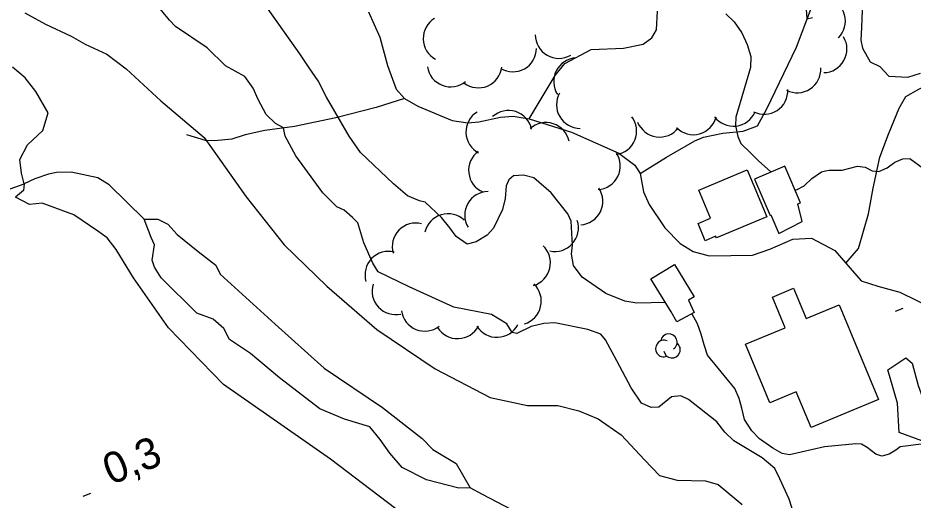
# Model space of a CAD drawing. Extents: x 362852 to 366875, y 5563573 to 5566479.
# Drawn here: x 363430.9 to 363544.5, y 5564422.3 to 5564483.5 of the extents above; entities that cross this region are included whole.
import ezdxf

# ---------------------------------------------------------------- set-up
doc = ezdxf.new("R2010")
doc.units = 0
for name, color, linetype in [('Niveau 19', 7, 'Continuous'), ('Niveau 2', 7, 'Continuous'), ('Niveau 22', 7, 'Continuous'), ('Niveau 3', 7, 'Continuous'), ('Niveau 31', 7, 'Continuous'), ('Niveau 4', 7, 'Continuous'), ('Niveau 44', 7, 'Continuous'), ('Niveau 7', 7, 'Continuous')]:
    doc.layers.add(name, color=color, linetype=linetype)

msp = doc.modelspace()

# ---------------------------------------------------------------- linework, layer by layer
at = {"layer": 'Niveau 19'}
msp.add_lwpolyline([(363555.06, 5564410.53), (363554.35, 5564413.76), (363552.74, 5564417.08), (363550.97, 5564420.84), (363547.82, 5564426.2), (363545.6, 5564429.8), (363542.71, 5564430.86), (363542.49, 5564434.61), (363541.27, 5564438.82), (363543.56, 5564440.35), (363544.37, 5564439.68), (363545.12, 5564436.85), (363545.65, 5564435.43), (363546.72, 5564433.62), (363550.3, 5564428.94), (363553.77, 5564422.9), (363555.22, 5564419.83), (363557.05, 5564416.78)], dxfattribs=at)
at = {"layer": 'Niveau 2'}
for points in [[(363469.58, 5564461.32), (363466.16, 5564466.03), (363464.8, 5564468.53), (363464.56, 5564469.55), (363463.56, 5564470.14), (363462.39, 5564471.28), (363461.35, 5564473.16), (363460.74, 5564474.6), (363459.68, 5564476.09), (363457.23, 5564477.45), (363454.89, 5564479.73), (363450.87, 5564482.43), (363450.1, 5564483.23), (363448.52, 5564485.2)], [(363530.86, 5564485.24), (363531, 5564483.42), (363531.74, 5564483.6)], [(363538.06, 5564485.57), (363537.92, 5564482.31), (363537.84, 5564480.71), (363538.08, 5564479.69), (363539.06, 5564477.96), (363540.26, 5564477.34), (363541.4, 5564476.13), (363543.82, 5564476.02), (363545.43, 5564476.51)], [(363482.58, 5564460.13), (363481.82, 5564460.31), (363480.31, 5564460.93), (363478.55, 5564462.44), (363474.36, 5564466.45), (363472.92, 5564468.53), (363470.04, 5564473.46), (363468.99, 5564475.52), (363467.85, 5564477.17), (363466.65, 5564478.98), (363462.54, 5564484.77)], [(363520.72, 5564484.04), (363521.77, 5564483.04), (363522.74, 5564481.64), (363523.42, 5564480.17), (363523.88, 5564478.61), (363523.84, 5564477.22), (363521.98, 5564470.93)], [(363521.98, 5564470.93), (363521.93, 5564469.84), (363522.26, 5564468.48), (363522.64, 5564467.57), (363523.9, 5564466.35), (363524.87, 5564465.38), (363526.44, 5564463.96)], [(363529.47, 5564461.74), (363529.67, 5564461.7), (363530.66, 5564462.18), (363531.63, 5564463.15), (363532.85, 5564463.97), (363533.35, 5564464.12), (363533.82, 5564464.19), (363535.5, 5564464.21), (363537.42, 5564464.71), (363538.42, 5564464.56), (363539.3, 5564464.12), (363540.14, 5564464.03), (363541.21, 5564464.48), (363542.16, 5564465.19), (363543.17, 5564465.62), (363544.08, 5564465.69), (363545.8, 5564464.41), (363547.73, 5564462.53)], [(363501.07, 5564457.7), (363500.66, 5564458.65), (363498.54, 5564461.33), (363496.36, 5564463.23), (363495.04, 5564463.55), (363493.77, 5564463.46), (363493.16, 5564462.95), (363492.86, 5564462.2), (363492.72, 5564460.58), (363492.37, 5564459.18), (363491.23, 5564456.82), (363490.42, 5564455.92), (363489.02, 5564455.08), (363487.89, 5564454.79), (363486.48, 5564455.76), (363485.7, 5564456.88), (363484.65, 5564458.19), (363482.58, 5564460.13)], [(363529.38, 5564420.42), (363528.74, 5564422.41), (363527.59, 5564424.99), (363526.92, 5564426.28), (363525.35, 5564427.63), (363521.74, 5564429.81), (363520.59, 5564430.9), (363519.59, 5564432.23), (363515.97, 5564435.04), (363515.02, 5564435.51), (363513.82, 5564435.39), (363512.23, 5564434.09), (363511.24, 5564434.05), (363510.01, 5564434.6), (363508.69, 5564436.56), (363506.87, 5564439.99), (363505.44, 5564442.65), (363504.84, 5564443.34), (363503.2, 5564443.97), (363499.03, 5564444.78), (363497.62, 5564444.7), (363496.02, 5564444.34), (363494.2, 5564443.45), (363493.59, 5564443.56), (363492.93, 5564444.67), (363490.99, 5564445.86), (363486.21, 5564446.8), (363480.55, 5564449.38), (363476.61, 5564451.29), (363475.91, 5564452.38), (363474.76, 5564454.97), (363474.02, 5564457.48), (363473.34, 5564458.19), (363472.26, 5564459.12), (363471.33, 5564459.54), (363469.58, 5564461.32)], [(363513.06, 5564447.36), (363509.43, 5564447.31), (363507.9, 5564447.54), (363505.48, 5564448.53), (363502.49, 5564450.59), (363501.37, 5564452.06), (363501.13, 5564453.53), (363501.28, 5564454.66), (363501.07, 5564457.7)], [(363545.83, 5564429.42), (363542.83, 5564429.04), (363542.31, 5564428.64), (363541.47, 5564428.1), (363540.5, 5564427.88), (363539.77, 5564428.13), (363538.66, 5564428.98), (363537.93, 5564429.37), (363537.21, 5564429.44), (363533.26, 5564429.03), (363528.8, 5564428.03), (363527.85, 5564428.2), (363526.68, 5564428.89), (363525, 5564430.07), (363524.01, 5564431.09), (363523.09, 5564432.52), (363522.75, 5564433.94), (363522.41, 5564435.18), (363521.88, 5564436.45), (363518.41, 5564440.69), (363517.98, 5564442.01), (363517.6, 5564443.36), (363517.12, 5564444.66), (363516.4, 5564445.97)]]:
    msp.add_lwpolyline(points, dxfattribs=at)
at = {"layer": 'Niveau 22'}
for points in [[(363509.85, 5564463.76), (363513.2, 5564465.86), (363516.77, 5564467.92), (363517.89, 5564468.39), (363520.35, 5564468.9), (363522.9, 5564469.13), (363524.72, 5564469.81), (363525.93, 5564472), (363529.68, 5564479.82), (363531.84, 5564485.53), (363533.38, 5564487.61), (363535.37, 5564491.01), (363537.09, 5564495.12), (363538.96, 5564504.55), (363539.15, 5564510.65), (363540.17, 5564515.15), (363540.56, 5564522.28), (363540.7, 5564529.49), (363541.26, 5564531.67), (363543.86, 5564536.02)], [(363475.38, 5564484.29), (363476.81, 5564481.07), (363477.79, 5564477.48), (363478.9, 5564474.5), (363479.95, 5564473.31), (363481.64, 5564472.33), (363485.97, 5564470.49), (363487.98, 5564470.19), (363489.36, 5564470.33), (363492.11, 5564470.93), (363493.75, 5564471.05), (363495.75, 5564470.71), (363501.12, 5564469.03), (363507.13, 5564466.37), (363509.15, 5564464.84), (363509.85, 5564463.76), (363510.29, 5564461.44), (363510.99, 5564459.85), (363512.99, 5564456.87), (363514.93, 5564454.87), (363516.59, 5564453.88), (363518.6, 5564453.29), (363524.11, 5564453.41), (363526.3, 5564454.15), (363529.23, 5564455.43), (363531.59, 5564455.54), (363534.54, 5564453.97), (363535.96, 5564452.36), (363537.9, 5564450.15), (363540.02, 5564449.44), (363542.79, 5564448.68), (363547.12, 5564446.56)], [(363495.75, 5564470.71), (363497.55, 5564473.66), (363499.08, 5564476.23), (363500.3, 5564477.75), (363503.64, 5564479.53), (363507.72, 5564479.69), (363510.24, 5564480.19), (363511.33, 5564481.02), (363511.91, 5564482.02), (363512.04, 5564484.39)], [(363535.96, 5564452.36), (363537.56, 5564454.25), (363538.81, 5564458.65), (363539.41, 5564461.9), (363540.28, 5564465.84), (363541.38, 5564468.78), (363542.74, 5564472.08), (363543.57, 5564473.54), (363545.21, 5564474.48), (363548.01, 5564475.79), (363551.55, 5564477.49)], [(363479.95, 5564473.31), (363476.34, 5564472.15), (363471.21, 5564470.84), (363465.96, 5564469.72), (363462.21, 5564469.24), (363459.72, 5564468.67), (363458.04, 5564468.14), (363455.83, 5564467.9), (363454.69, 5564467.98), (363452.3, 5564468.68)]]:
    msp.add_lwpolyline(points, dxfattribs=at)
at = {"layer": 'Niveau 3'}
for p, q in [((363542.27, 5564446.28), (363543.23, 5564446.67)), ((363439.16, 5564422.79), (363440.12, 5564423.18))]:
    msp.add_line(p, q, dxfattribs=at)
at = {"layer": 'Niveau 31'}
for points in [[(363530.4, 5564457.65), (363529.87, 5564459.9), (363530.2, 5564460.05), (363528.2, 5564464.71), (363524.35, 5564463.06), (363526.33, 5564458.45), (363526.45, 5564458.5), (363527.46, 5564456.14), (363530.4, 5564457.65)], [(363513.77, 5564446.18), (363511.22, 5564450.38), (363514.2, 5564452.19), (363516.69, 5564448.11), (363515.97, 5564447.67), (363516.69, 5564446.13), (363514.52, 5564444.92), (363513.77, 5564446.18)], [(363535.1, 5564447.08), (363540.09, 5564435.04), (363531.54, 5564431.49), (363529.66, 5564436.02), (363526.32, 5564434.64), (363523.22, 5564442.1), (363528.24, 5564444.18), (363526.63, 5564448.06), (363529.33, 5564449.19), (363530.93, 5564445.35), (363535.1, 5564447.08)]]:
    msp.add_lwpolyline(points, dxfattribs=at)
msp.add_lwpolyline([(363519.43, 5564455.79), (363518.11, 5564455.23), (363517.19, 5564457.43), (363518.78, 5564458.1), (363517.29, 5564461.64), (363523.43, 5564464.22), (363525.93, 5564458.27), (363519.52, 5564455.58), (363519.43, 5564455.79)], close=True, dxfattribs=at)
at = {"layer": 'Niveau 4'}
for points in [[(363446.88, 5564457.97), (363442.47, 5564462.33), (363441.03, 5564463.23), (363437.62, 5564463.93), (363435.75, 5564463.9), (363434.77, 5564463.68), (363433.02, 5564463.07), (363431.68, 5564462.44)], [(363429.87, 5564461.81), (363431.68, 5564462.44), (363431.6, 5564461.59), (363430.56, 5564460.78)], [(363446.88, 5564457.97), (363448.65, 5564457.95), (363449.9, 5564457.35), (363451.09, 5564456.03), (363453.75, 5564453.88), (363455.99, 5564452.12), (363456.54, 5564450.97), (363463.54, 5564444.61), (363469.72, 5564439.04), (363477.15, 5564434.06), (363482.2, 5564430.09), (363483.54, 5564428.7), (363486.48, 5564426.93), (363488.28, 5564423.85), (363486.85, 5564423.81), (363482.71, 5564424.84), (363479.65, 5564426.44), (363478.08, 5564428.24), (363476.85, 5564429.98), (363475.55, 5564431.57), (363472.32, 5564432.54), (363469.19, 5564433.86), (363464.08, 5564437.8), (363460.39, 5564440.9), (363457.71, 5564442.66), (363456.99, 5564444.06), (363455.67, 5564445.26), (363453.59, 5564446.03), (363449.07, 5564450.53), (363448.19, 5564451.86), (363447.89, 5564452.74), (363448.2, 5564454.69), (363447.79, 5564455.65), (363446.88, 5564457.97)], [(363493.54, 5564421.04), (363489.83, 5564422.99), (363488.28, 5564423.85)]]:
    msp.add_lwpolyline(points, dxfattribs=at)
at = {"layer": 'Niveau 44'}
for centre, radius, start, end in [((363532.89, 5564483.13), 3, 315.1602, 75.1381), ((363485.31, 5564480.91), 3, 121.3972, 241.3751), ((363499.53, 5564481.39), 3, 180.1325, 300.1104), ((363533.09, 5564479.58), 3, 270.9667, 30.9447), ((363493.69, 5564479.69), 3, 239.1757, 359.1536), ((363501.87, 5564475.45), 3, 93.1178, 213.0957), ((363485.8, 5564477.77), 3, 188.9221, 308.9001), ((363489.32, 5564477.65), 3, 232.6902, 352.6682), ((363529.78, 5564477.02), 3, 243.0266, 3.0045), ((363502.23, 5564472.49), 3, 150.0713, 270.0492), ((363525.59, 5564474.29), 3, 243.0266, 3.0045), ((363490.74, 5564469.04), 3, 122.1568, 242.1348), ((363493.13, 5564468.77), 3, 12.1946, 132.1726), ((363521.68, 5564472.78), 3, 216.8693, 336.8473), ((363497.89, 5564467.24), 3, 12.1946, 132.1726), ((363506.4, 5564469.15), 3, 277.7428, 37.7208), ((363512.31, 5564471.4), 3, 201.8912, 321.8692), ((363516.58, 5564471.7), 3, 225.4954, 345.4733), ((363491.08, 5564464.17), 3, 126.4598, 246.4377), ((363504.33, 5564464.72), 3, 273.698, 33.676), ((363490.58, 5564458.48), 3, 90.628, 210.6059), ((363502.11, 5564460.24), 3, 273.698, 33.676), ((363485.46, 5564455.65), 3, 46.8933, 166.8712), ((363499.01, 5564456.86), 3, 257.9365, 17.9144), ((363481.39, 5564454.48), 3, 76.1878, 196.1658), ((363495.46, 5564452.42), 3, 286.5547, 46.5326), ((363477.93, 5564450.88), 3, 76.1878, 196.1658), ((363478.82, 5564448.84), 3, 162.9759, 282.9539), ((363494.3, 5564447.55), 3, 286.5547, 46.5326), ((363482.52, 5564446.74), 3, 187.8026, 307.7805), ((363486.68, 5564445.79), 3, 211.9628, 331.9408), ((363491.68, 5564445.96), 3, 211.9628, 331.9408), ((363513.49, 5564442.35), 1.05, 304.3592, 171.8163), ((363512.85, 5564441.53), 1.05, 66.2054, 291.894), ((363513.89, 5564441.38), 1.05, 189.0269, 51.7112)]:
    msp.add_arc(centre, radius, start, end, dxfattribs=at)
at = {"layer": 'Niveau 7'}
for points in [[(363431.77, 5564484.16), (363434.37, 5564482.74), (363437.65, 5564481.23), (363439.39, 5564480.2), (363442.14, 5564478.91), (363444.59, 5564477.05), (363448.99, 5564473), (363454.52, 5564468.35), (363459.86, 5564460.79), (363464.68, 5564454.72), (363470.1, 5564449.47), (363476.42, 5564443.95), (363483.82, 5564438.96), (363490.82, 5564435.31), (363495.53, 5564434.29), (363499.4, 5564434.29), (363502.05, 5564433.64), (363504.52, 5564432.6), (363507.45, 5564430.57), (363510.4, 5564427.41), (363512.29, 5564425.39), (363514.54, 5564424.83), (363518.16, 5564424.73), (363519.74, 5564424.27), (363522.79, 5564421.73)], [(363431.68, 5564462.44), (363431.34, 5564463.82), (363431.13, 5564465.55), (363432.09, 5564467.4), (363434.03, 5564469.22), (363434.72, 5564471.46), (363433.15, 5564474.19), (363431.79, 5564475.94), (363430.17, 5564477.27)], [(363487.86, 5564406.59), (363489.66, 5564408.34), (363491.99, 5564409.62), (363491.85, 5564410.25), (363487.81, 5564414.7), (363485, 5564416.47), (363470.55, 5564427.49), (363456.96, 5564436.98), (363449.99, 5564444.16), (363445.56, 5564450.52), (363443.33, 5564454.1), (363442.21, 5564455.58), (363441.02, 5564456.46), (363437.96, 5564458.5), (363433.94, 5564460.02), (363432.34, 5564459.84), (363430.56, 5564460.78)]]:
    msp.add_lwpolyline(points, dxfattribs=at)

# ---------------------------------------------------------------- texts
at = {"layer": 'Niveau 3'}
msp.add_text('0,3  ', height=3.93, rotation=22.09, dxfattribs=at).set_placement((363442.67, 5564424.15))

doc.saveas('drawing.dxf')
